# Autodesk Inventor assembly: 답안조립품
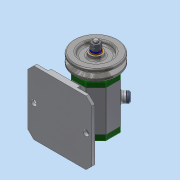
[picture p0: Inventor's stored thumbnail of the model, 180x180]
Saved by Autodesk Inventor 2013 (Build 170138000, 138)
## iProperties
Created: 2018-06
Part Number: 답안조립품
Document SubType Name: Assembly
Designer: Administrator
Author: Administrator
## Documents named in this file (16)
- C:\Users\Administrator\Desktop\480608V1021\답안조립품.iam
- C:\Users\Administrator\Desktop\480608V1021\V벨트풀리.ipt
- C:\Users\Administrator\Desktop\480608V1021\고무캡.ipt
- C:\Users\Administrator\Desktop\480608V1021\너트 M8.ipt
- 너트 M8.ipt
- C:\Users\Administrator\Desktop\480608V1021\뒤커버.ipt
- C:\Users\Administrator\Desktop\480608V1021\베어링 15x32x9.ipt
- C:\Users\Administrator\Desktop\480608V1021\본체.ipt
- C:\Users\Administrator\Desktop\480608V1021\볼트 M4x12.ipt
- C:\Users\Administrator\Desktop\480608V1021\스프링와셔 8.ipt
- C:\Users\Administrator\Desktop\480608V1021\앞커버.ipt
- C:\Users\Administrator\Desktop\480608V1021\오일 실 15 25 7.ipt
- C:\Users\Administrator\Desktop\480608V1021\와셔 8x17.ipt
- C:\Users\Administrator\Desktop\480608V1021\축.ipt
- C:\Users\Administrator\Desktop\480608V1021\키 3x3x12.ipt
- 키 3x3x12.ipt
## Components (2 placed, 2 different names)
1. V벨트풀리:1
2. 고무캡:1
